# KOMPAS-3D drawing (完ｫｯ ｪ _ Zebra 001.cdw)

Views: Спереди 1, Спереди, Проекционный вид 2, Разрез А-А, Вид 4, Диметрия, Вид 5
Referenced files in D:\работа\Чертежи\Компенсатор\Пламегаситель Свечка\: Колпак.m3d, Колпак _ Zebra 001.cdw
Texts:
  Zebra 001
  Колпак
  Александр
  Рифление
  прямое
  Лит-Масса-Масштаб
  Материал-Предприятие
  Title Specification
  Body Specification ( left align )
  Body Specificaton ( centered )
  Поз.
  Кол.
  Приме-
  чание
  Таблица спецификации
  Сталь 20  ГОСТ 1050-88
  Чередниченко А.В.
  Zebra 001-
Dimensions and other numbers on the sheet: 2; 120; 24; 18Х1; 30; 3; 27,2; 7; 70; 10 отверстий; 4; 1; 0; 1:1; 0,09; 19.06.2015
